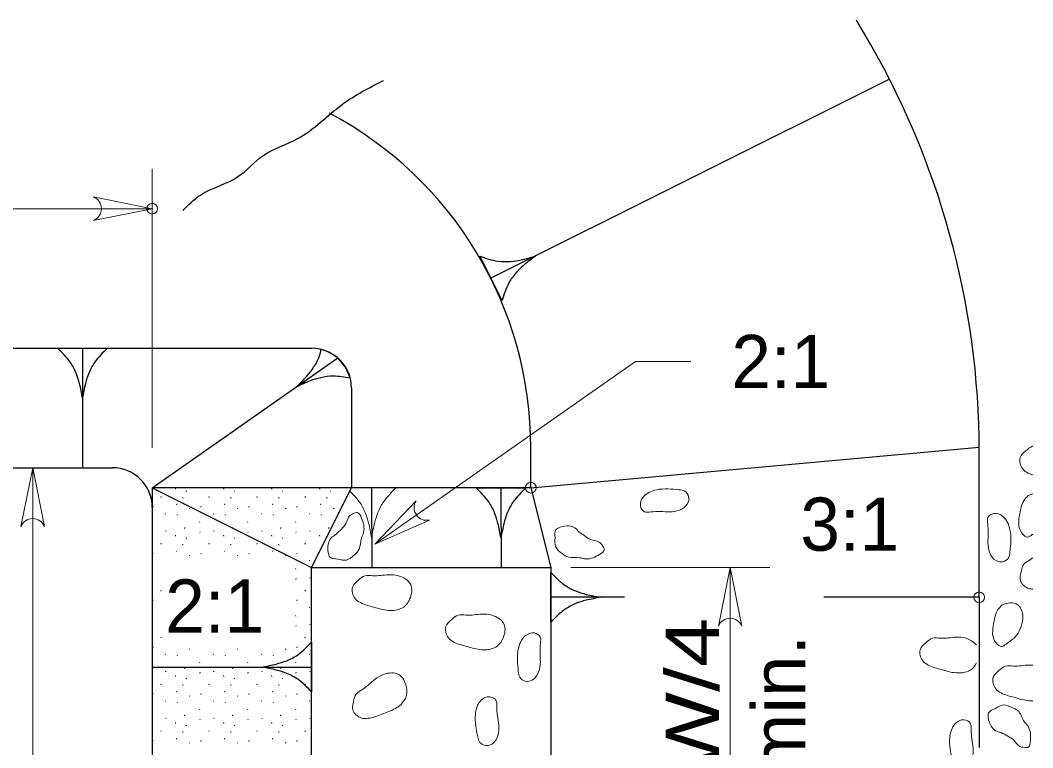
# Model space of a CAD drawing. Extents: x 1043.1 to 1101.1, y 672.4 to 716.4.
# Drawn here: x 1060.033 to 1063.081, y 704.187 to 706.376 of the extents above; entities that cross this region are included whole.
import ezdxf

# ---------------------------------------------------------------- set-up
doc = ezdxf.new("R2010")
doc.units = 0
doc.header["$LTSCALE"] = 0.064
doc.header["$PDMODE"] = 32
doc.header["$PDSIZE"] = 0.032
doc.layers.add('1', color=7, linetype='Continuous', lineweight=13)

msp = doc.modelspace()

# ---------------------------------------------------------------- linework, layer by layer
at = {"layer": '1', "lineweight": 25}
for p, q in [((1062.64925, 706.19908), (1061.44983, 705.5995)), ((1061.48333, 705.53242), (1061.41633, 705.6665)), ((1060.14583, 705.38908), (1060.29575, 705.38908)), ((1060.22075, 705.38908), (1060.22075, 705.02725)), ((1060.43058, 704.96942), (1060.98883, 705.36)), ((1061.03033, 705.26925), (1061.03033, 704.96942)), ((1062.91942, 704.63958), (1062.91942, 705.11933)), ((1061.57008, 704.96942), (1062.91892, 705.09175)), ((1061.57008, 704.96942), (1061.57008, 705.08933)), ((1058.45158, 705.02933), (1060.31075, 705.02933)), ((1060.43058, 704.96942), (1060.91042, 704.7295)), ((1061.09033, 704.96942), (1061.09125, 704.7285)), ((1061.40525, 704.9685), (1061.55508, 704.9685)), ((1061.48008, 704.9685), (1061.48025, 704.72875)), ((1060.91042, 704.7295), (1061.63, 704.7295)), ((1061.63, 704.56458), (1061.63, 704.7145)), ((1061.85183, 704.63958), (1061.63, 704.63958)), ((1062.91942, 704.63958), (1062.45225, 704.63958)), ((1062.91942, 704.63958), (1062.91942, 704.18808)), ((1060.91042, 704.50458), (1060.91042, 704.35475)), ((1060.43058, 704.42975), (1060.91042, 704.42975))]:
    msp.add_line(p, q, dxfattribs=at)
at = {"layer": '1'}
for p, q in [((1060.43058, 705.92883), (1060.43058, 705.08933)), ((1058.33175, 705.80883), (1060.43058, 705.80883)), ((1060.50083, 704.96775), (1060.50108, 704.96492)), ((1060.64542, 704.96775), (1060.64575, 704.96492)), ((1060.79, 704.96775), (1060.79033, 704.96492)), ((1060.9345, 704.96775), (1060.93483, 704.96492)), ((1060.4565, 704.94025), (1060.45775, 704.94292)), ((1060.52142, 704.94025), (1060.52258, 704.93842)), ((1060.52258, 704.9395), (1060.52392, 704.93775)), ((1060.53225, 704.95975), (1060.53342, 704.95783)), ((1060.601, 704.94025), (1060.60233, 704.94292)), ((1060.666, 704.94025), (1060.66725, 704.93842)), ((1060.66725, 704.9395), (1060.66842, 704.93775)), ((1060.67675, 704.95975), (1060.67792, 704.95783)), ((1060.74575, 704.94025), (1060.74692, 704.94292)), ((1060.8105, 704.94025), (1060.81175, 704.93842)), ((1060.81175, 704.9395), (1060.81292, 704.93775)), ((1060.82125, 704.95975), (1060.82242, 704.95783)), ((1060.89025, 704.94025), (1060.89142, 704.94292)), ((1060.95508, 704.94025), (1060.95633, 704.93842)), ((1060.95633, 704.9395), (1060.9575, 704.93775)), ((1060.96592, 704.95975), (1060.96708, 704.95783)), ((1063.0805, 704.95133), (1063.06708, 704.94608)), ((1060.43208, 704.91092), (1060.43333, 704.91358)), ((1060.50358, 704.91783), (1060.50483, 704.92058)), ((1060.54292, 704.90742), (1060.54408, 704.90558)), ((1060.57675, 704.91092), (1060.57792, 704.91358)), ((1060.64808, 704.91783), (1060.64942, 704.92058)), ((1060.68742, 704.90742), (1060.68858, 704.90558)), ((1060.72125, 704.91092), (1060.72242, 704.91358)), ((1060.79283, 704.91783), (1060.794, 704.92058)), ((1060.832, 704.90742), (1060.83325, 704.90558)), ((1060.86575, 704.91092), (1060.867, 704.91358)), ((1060.93733, 704.91783), (1060.9385, 704.92058)), ((1060.97658, 704.90742), (1060.97783, 704.90558)), ((1060.46983, 704.89158), (1060.471, 704.88983)), ((1060.5055, 704.88833), (1060.50675, 704.8865)), ((1060.61433, 704.89158), (1060.6155, 704.88983)), ((1060.65, 704.88833), (1060.65125, 704.8865)), ((1060.759, 704.89158), (1060.76025, 704.88983)), ((1060.79458, 704.88833), (1060.79592, 704.8865)), ((1060.9035, 704.89158), (1060.90475, 704.88983)), ((1060.93925, 704.88833), (1060.94042, 704.8865)), ((1060.52783, 704.84658), (1060.529, 704.84933)), ((1060.57275, 704.86692), (1060.57392, 704.86508)), ((1060.67233, 704.84658), (1060.6735, 704.84933)), ((1060.71725, 704.86692), (1060.71842, 704.86508)), ((1060.81683, 704.84658), (1060.818, 704.84933)), ((1060.86175, 704.86692), (1060.86292, 704.86508)), ((1060.9615, 704.84658), (1060.96275, 704.84933)), ((1060.47092, 704.84008), (1060.47208, 704.83825)), ((1060.50083, 704.82658), (1060.50108, 704.82392)), ((1060.53225, 704.81858), (1060.53342, 704.81692)), ((1060.57375, 704.83425), (1060.57492, 704.83692)), ((1060.6155, 704.84008), (1060.61675, 704.83825)), ((1060.64542, 704.82658), (1060.64575, 704.82392)), ((1060.67675, 704.81858), (1060.67792, 704.81692)), ((1060.71825, 704.83425), (1060.71942, 704.83692)), ((1060.76008, 704.84008), (1060.76133, 704.83825)), ((1060.79, 704.82658), (1060.79033, 704.82392)), ((1060.82125, 704.81858), (1060.82242, 704.81692)), ((1060.86275, 704.83425), (1060.86392, 704.83692)), ((1060.90458, 704.84008), (1060.90583, 704.83825)), ((1060.9345, 704.82658), (1060.93483, 704.82392)), ((1060.4565, 704.79933), (1060.45775, 704.802)), ((1060.52142, 704.79933), (1060.52258, 704.7975)), ((1060.52258, 704.79858), (1060.52392, 704.79683)), ((1060.601, 704.79933), (1060.60233, 704.802)), ((1060.666, 704.79933), (1060.66725, 704.7975)), ((1060.66725, 704.79858), (1060.66842, 704.79683)), ((1060.74575, 704.79933), (1060.74692, 704.802)), ((1060.8105, 704.79933), (1060.81175, 704.7975)), ((1060.81175, 704.79858), (1060.81292, 704.79683)), ((1060.89025, 704.79933), (1060.89142, 704.802)), ((1060.43208, 704.77), (1060.43333, 704.77275)), ((1060.50358, 704.77692), (1060.50483, 704.77958)), ((1060.54292, 704.76642), (1060.54408, 704.76458)), ((1060.57675, 704.77), (1060.57792, 704.77275)), ((1060.64808, 704.77692), (1060.64942, 704.77958)), ((1060.68742, 704.76642), (1060.68858, 704.76458)), ((1060.72125, 704.77), (1060.72242, 704.77275)), ((1060.79283, 704.77692), (1060.794, 704.77958)), ((1060.832, 704.76642), (1060.83325, 704.76458)), ((1060.86575, 704.77), (1060.867, 704.77275)), ((1060.86175, 704.72592), (1060.86292, 704.72408)), ((1060.9035, 704.75058), (1060.90475, 704.74883)), ((1061.69, 704.7295), (1062.28975, 704.7295)), ((1062.16983, 704.7295), (1062.16983, 704.00992)), ((1060.86275, 704.69333), (1060.86392, 704.696)), ((1060.90458, 704.69908), (1060.90583, 704.69733)), ((1060.4565, 704.65825), (1060.45775, 704.661)), ((1060.89025, 704.65825), (1060.89142, 704.661)), ((1060.43208, 704.629), (1060.43333, 704.63175)), ((1060.86575, 704.629), (1060.867, 704.63175)), ((1060.9035, 704.60975), (1060.90475, 704.60792)), ((1060.86175, 704.585), (1060.86292, 704.58325)), ((1060.86275, 704.55233), (1060.86392, 704.55508)), ((1060.90458, 704.55825), (1060.90583, 704.55642)), ((1060.4565, 704.51733), (1060.45775, 704.52)), ((1060.89025, 704.51733), (1060.89142, 704.52)), ((1060.43208, 704.488), (1060.43333, 704.49075)), ((1060.54292, 704.48458), (1060.54408, 704.48275)), ((1060.68742, 704.48458), (1060.68858, 704.48275)), ((1060.832, 704.48458), (1060.83325, 704.48275)), ((1060.86575, 704.488), (1060.867, 704.49075)), ((1060.46983, 704.46883), (1060.471, 704.467)), ((1060.5055, 704.4655), (1060.50675, 704.46375)), ((1060.61433, 704.46883), (1060.6155, 704.467)), ((1060.65, 704.4655), (1060.65125, 704.46375)), ((1060.759, 704.46883), (1060.76025, 704.467)), ((1060.79458, 704.4655), (1060.79592, 704.46375)), ((1060.9035, 704.46883), (1060.90475, 704.467)), ((1060.47092, 704.41725), (1060.47208, 704.41542)), ((1060.52783, 704.42383), (1060.529, 704.4265)), ((1060.57275, 704.44408), (1060.57392, 704.44225)), ((1060.6155, 704.41725), (1060.61675, 704.41542)), ((1060.67233, 704.42383), (1060.6735, 704.4265)), ((1060.71725, 704.44408), (1060.71842, 704.44225)), ((1060.76008, 704.41725), (1060.76133, 704.41542)), ((1060.81683, 704.42383), (1060.818, 704.4265)), ((1060.86175, 704.44408), (1060.86292, 704.44225)), ((1060.90458, 704.41725), (1060.90583, 704.41542)), ((1060.50083, 704.40383), (1060.50108, 704.40108)), ((1060.53225, 704.39583), (1060.53342, 704.394)), ((1060.57375, 704.41142), (1060.57492, 704.41408)), ((1060.64542, 704.40383), (1060.64575, 704.40108)), ((1060.67675, 704.39583), (1060.67792, 704.394)), ((1060.71825, 704.41142), (1060.71942, 704.41408)), ((1060.79, 704.40383), (1060.79033, 704.40108)), ((1060.82125, 704.39583), (1060.82242, 704.394)), ((1060.86275, 704.41142), (1060.86392, 704.41408)), ((1060.4565, 704.37642), (1060.45775, 704.37908)), ((1060.50358, 704.354), (1060.50483, 704.35675)), ((1060.52142, 704.37642), (1060.52258, 704.37458)), ((1060.52258, 704.37575), (1060.52392, 704.37392)), ((1060.601, 704.37642), (1060.60233, 704.37908)), ((1060.64808, 704.354), (1060.64942, 704.35675)), ((1060.666, 704.37642), (1060.66725, 704.37458)), ((1060.66725, 704.37575), (1060.66842, 704.37392)), ((1060.74575, 704.37642), (1060.74692, 704.37908)), ((1060.79283, 704.354), (1060.794, 704.35675)), ((1060.8105, 704.37642), (1060.81175, 704.37458)), ((1060.81175, 704.37575), (1060.81292, 704.37392)), ((1060.89025, 704.37642), (1060.89142, 704.37908)), ((1060.43208, 704.347), (1060.43333, 704.34983)), ((1060.46983, 704.32775), (1060.471, 704.32592)), ((1060.54292, 704.3435), (1060.54408, 704.34175)), ((1060.57675, 704.347), (1060.57792, 704.34983)), ((1060.61433, 704.32775), (1060.6155, 704.32592)), ((1060.68742, 704.3435), (1060.68858, 704.34175)), ((1060.72125, 704.347), (1060.72242, 704.34983)), ((1060.759, 704.32775), (1060.76025, 704.32592)), ((1060.832, 704.3435), (1060.83325, 704.34175)), ((1060.86575, 704.347), (1060.867, 704.34983)), ((1060.9035, 704.32775), (1060.90475, 704.32592)), ((1060.5055, 704.3245), (1060.50675, 704.32258)), ((1060.57275, 704.30308), (1060.57392, 704.30133)), ((1060.65, 704.3245), (1060.65125, 704.32258)), ((1060.71725, 704.30308), (1060.71842, 704.30133)), ((1060.79458, 704.3245), (1060.79592, 704.32258)), ((1060.86175, 704.30308), (1060.86292, 704.30133)), ((1060.47092, 704.27633), (1060.47208, 704.2745)), ((1060.52783, 704.28283), (1060.529, 704.28558)), ((1060.57375, 704.2705), (1060.57492, 704.27325)), ((1060.6155, 704.27633), (1060.61675, 704.2745)), ((1060.67233, 704.28283), (1060.6735, 704.28558)), ((1060.71825, 704.2705), (1060.71942, 704.27325)), ((1060.76008, 704.27633), (1060.76133, 704.2745)), ((1060.81683, 704.28283), (1060.818, 704.28558)), ((1060.86275, 704.2705), (1060.86392, 704.27325)), ((1060.90458, 704.27633), (1060.90583, 704.2745)), ((1060.4565, 704.23542), (1060.45775, 704.23825)), ((1060.50083, 704.26292), (1060.50108, 704.26025)), ((1060.52142, 704.23542), (1060.52258, 704.23358)), ((1060.52258, 704.23475), (1060.52392, 704.23292)), ((1060.53225, 704.25492), (1060.53342, 704.25308)), ((1060.601, 704.23542), (1060.60233, 704.23825)), ((1060.64542, 704.26292), (1060.64575, 704.26025)), ((1060.666, 704.23542), (1060.66725, 704.23358)), ((1060.66725, 704.23475), (1060.66842, 704.23292)), ((1060.67675, 704.25492), (1060.67792, 704.25308)), ((1060.74575, 704.23542), (1060.74692, 704.23825)), ((1060.79, 704.26292), (1060.79033, 704.26025)), ((1060.8105, 704.23542), (1060.81175, 704.23358)), ((1060.81175, 704.23475), (1060.81292, 704.23292)), ((1060.82125, 704.25492), (1060.82242, 704.25308)), ((1060.89025, 704.23542), (1060.89142, 704.23825)), ((1060.43208, 704.20608), (1060.43333, 704.20883)), ((1060.50358, 704.21308), (1060.50483, 704.21583)), ((1060.57675, 704.20608), (1060.57792, 704.20883)), ((1060.64808, 704.21308), (1060.64942, 704.21583)), ((1060.72125, 704.20608), (1060.72242, 704.20883)), ((1060.79283, 704.21308), (1060.794, 704.21583)), ((1060.86575, 704.20608), (1060.867, 704.20883)), ((1060.54292, 704.20258), (1060.54408, 704.20083)), ((1060.68742, 704.20258), (1060.68858, 704.20083)), ((1060.832, 704.20258), (1060.83325, 704.20083))]:
    msp.add_line(p, q, dxfattribs=at)
for points in [[(1060.254, 705.84417), (1060.43058, 705.80883), (1060.254, 705.77358), (1060.254, 705.77367)], [(1061.10033, 704.79983), (1061.88458, 705.34892), (1062.05125, 705.34892)], [(1060.0355, 704.85275), (1060.07083, 705.02933), (1060.10617, 704.85275), (1060.10608, 704.85275)], [(1060.07083, 705.02933), (1060.07083, 704.30983), (1060.07083, 703.83)], [(1061.16533, 704.96975), (1061.0305, 704.96933), (1061.025, 704.95908)], [(1061.26517, 704.87217), (1061.10033, 704.79983), (1061.22467, 704.93), (1061.22467, 704.92992)], [(1062.1345, 704.55292), (1062.16983, 704.7295), (1062.20517, 704.55292), (1062.20508, 704.55292)]]:
    msp.add_lwpolyline(points, dxfattribs=at)
at = {"layer": '1', "lineweight": 25}
for points in [[(1057.91192, 705.38908), (1059.41108, 705.38908), (1060.91042, 705.38908)], [(1061.02583, 705.2995), (1061.01208, 705.3325), (1060.98942, 705.35975), (1060.96225, 705.37708), (1060.9375, 705.3865)], [(1060.43058, 704.96942), (1060.43058, 704.90942), (1060.43058, 703.95), (1060.43058, 703.89), (1061.03033, 703.77008)], [(1061.57008, 704.96942), (1061.39808, 704.96942), (1060.43058, 704.96942)], [(1061.03033, 703.77008), (1060.91042, 704.00992), (1060.91042, 704.7295), (1061.03033, 704.96942)], [(1061.57008, 704.96942), (1061.63, 704.7295), (1061.63, 704.00992), (1061.57008, 703.77008)]]:
    msp.add_lwpolyline(points, dxfattribs=at)
at = {"layer": '1'}
for centre, start, end in [((1060.23967, 705.80894), 292.08789, 67.91402), ((1061.25669, 704.90927), 147.08522, 282.91135), ((1060.0708, 704.83842), 22.08789, 157.91402), ((1062.1698, 704.53859), 22.08789, 157.91402)]:
    msp.add_arc(centre, 0.03811, start, end, dxfattribs=at)
at = {"layer": '1', "lineweight": 25}
for centre, major_axis, start_param, end_param in [((1060.43863, 705.07247), (2.48123, 0), 0.0188725, 0.5531943), ((1060.43065, 705.0893), (1.13943, 0), 6.2831853, 7.3670824), ((1060.91041, 705.26919), (0.11994, 0), 6.2831853, 7.8539816), ((1060.31071, 704.90941), (0.11994, 0), 6.2831853, 7.8539816)]:
    msp.add_ellipse(centre, major_axis=major_axis, ratio=0.999895, start_param=start_param, end_param=end_param, dxfattribs=at)
for points in [[(1060.5225, 705.80342), (1060.57425, 705.84908), (1060.68858, 705.90542), (1060.76333, 705.96792), (1060.8685, 706.02), (1061.0025, 706.12283), (1061.12642, 706.19475)], [(1061.41633, 705.6665), (1061.471, 705.65108), (1061.50842, 705.65008), (1061.54092, 705.655), (1061.584, 705.6665)], [(1061.584, 705.6665), (1061.549, 705.639), (1061.5255, 705.616), (1061.50392, 705.58542), (1061.48333, 705.53242)], [(1060.22075, 705.23925), (1060.21175, 705.28283), (1060.20158, 705.31408), (1060.184, 705.347), (1060.14583, 705.38908)], [(1060.29575, 705.38908), (1060.2575, 705.347), (1060.23983, 705.31408), (1060.22975, 705.28283), (1060.22075, 705.23925)], [(1060.9375, 705.3865), (1060.93325, 705.366), (1060.91633, 705.33258), (1060.8965, 705.3065), (1060.86592, 705.27408)], [(1060.86592, 705.27408), (1060.90683, 705.29175), (1060.93825, 705.30142), (1060.97542, 705.30583), (1061.02583, 705.2995)], [(1061.48025, 704.8185), (1061.47108, 704.86208), (1061.461, 704.89342), (1061.44333, 704.92642), (1061.40525, 704.9685)], [(1061.55508, 704.9685), (1061.51692, 704.92642), (1061.49925, 704.89342), (1061.48908, 704.86208), (1061.48025, 704.8185)], [(1061.63, 704.7145), (1061.67208, 704.67633), (1061.70508, 704.65858), (1061.73642, 704.6485), (1061.78, 704.63958)], [(1061.78, 704.63958), (1061.73642, 704.63058), (1061.70508, 704.6205), (1061.67208, 704.60283), (1061.63, 704.56458)], [(1060.7605, 704.42975), (1060.80408, 704.43875), (1060.83533, 704.44883), (1060.86833, 704.4665), (1060.91042, 704.50458)], [(1060.91042, 704.35475), (1060.86833, 704.39292), (1060.83533, 704.41058), (1060.80408, 704.42075), (1060.7605, 704.42975)]]:
    msp.add_spline(points, degree=3, dxfattribs=at)
at = {"layer": '1'}
for points in [[(1063.0805, 705.09425), (1063.07992, 705.09408), (1063.05958, 705.08042), (1063.04283, 705.06025), (1063.05025, 705.02583), (1063.06633, 705.01325), (1063.0805, 705.00792)], [(1061.09092, 704.8195), (1061.09975, 704.863), (1061.10975, 704.89442), (1061.12733, 704.92742), (1061.16533, 704.96975)], [(1061.98775, 704.89633), (1062.01683, 704.90175), (1062.04158, 704.92108), (1062.045, 704.94192), (1062.03333, 704.95892), (1062.01608, 704.96308), (1061.94875, 704.96308), (1061.90858, 704.94192), (1061.89992, 704.9145), (1061.91208, 704.89692), (1061.93108, 704.89633), (1061.98775, 704.89633)], [(1061.025, 704.95908), (1061.05375, 704.92725), (1061.0715, 704.89425), (1061.08175, 704.863), (1061.09092, 704.8195)], [(1063.06708, 704.94608), (1063.05333, 704.93025), (1063.04442, 704.90533), (1063.039, 704.87483), (1063.04058, 704.84683), (1063.04992, 704.83058), (1063.06442, 704.82083), (1063.07883, 704.82842), (1063.0805, 704.8295)], [(1061.067, 704.85783), (1061.06058, 704.878), (1061.04733, 704.89483), (1061.03725, 704.89183), (1061.02475, 704.88458), (1061.01342, 704.86175), (1060.99975, 704.84492), (1060.98292, 704.82833), (1060.9695, 704.81825), (1060.96075, 704.80133), (1060.95992, 704.77475), (1060.96542, 704.76083), (1060.98875, 704.75408), (1061.01525, 704.75158), (1061.03908, 704.76775), (1061.05308, 704.784), (1061.06008, 704.8175), (1061.06675, 704.83425), (1061.067, 704.85783)], [(1062.94508, 704.80408), (1062.9505, 704.775), (1062.96992, 704.75008), (1062.99075, 704.74675), (1063.00775, 704.7585), (1063.01192, 704.77575), (1063.01192, 704.843), (1062.99075, 704.88308), (1062.96333, 704.89183), (1062.94575, 704.87958), (1062.94508, 704.86058), (1062.94508, 704.80408)], [(1061.75783, 704.75858), (1061.77683, 704.76842), (1061.79125, 704.78408), (1061.78642, 704.79375), (1061.77742, 704.80483), (1061.75283, 704.81208), (1061.73425, 704.82292), (1061.71492, 704.83675), (1061.70283, 704.84833), (1061.6845, 704.85433), (1061.65825, 704.85042), (1061.64542, 704.84283), (1061.64275, 704.81875), (1061.6445, 704.792), (1061.66458, 704.77108), (1061.68292, 704.76025), (1061.71708, 704.75875), (1061.7345, 704.755), (1061.75783, 704.75858)], [(1063.0805, 704.7585), (1063.073, 704.7525), (1063.05392, 704.73892), (1063.04533, 704.71592), (1063.04342, 704.68975), (1063.06942, 704.666), (1063.0805, 704.664)], [(1061.16192, 704.6005), (1061.184, 704.60808), (1061.20533, 704.63375), (1061.20842, 704.67775), (1061.17175, 704.70433), (1061.14158, 704.70742), (1061.09442, 704.70433), (1061.07092, 704.70433), (1061.05058, 704.69058), (1061.03383, 704.67042), (1061.04125, 704.63608), (1061.05733, 704.6235), (1061.09792, 704.60992), (1061.14158, 704.60008), (1061.16192, 704.6005)], [(1062.9885, 704.61658), (1062.97475, 704.60075), (1062.96583, 704.57583), (1062.96042, 704.54533), (1062.962, 704.51733), (1062.97133, 704.50108), (1062.98583, 704.49125), (1063.00025, 704.49892), (1063.02458, 704.51683), (1063.03958, 704.53742), (1063.04933, 704.567), (1063.04692, 704.601), (1063.03533, 704.61733), (1063.01242, 704.623), (1062.9885, 704.61658)], [(1061.4425, 704.48208), (1061.46458, 704.48975), (1061.48592, 704.51525), (1061.48908, 704.55933), (1061.45233, 704.58592), (1061.42225, 704.589), (1061.37508, 704.58592), (1061.35158, 704.58592), (1061.33133, 704.57225), (1061.3145, 704.552), (1061.32192, 704.51758), (1061.338, 704.505), (1061.37858, 704.49142), (1061.42225, 704.48175), (1061.4425, 704.48208)], [(1061.599, 704.44458), (1061.59358, 704.4155), (1061.57425, 704.39058), (1061.55342, 704.38725), (1061.53642, 704.399), (1061.53225, 704.41625), (1061.53225, 704.48358), (1061.55342, 704.52358), (1061.58083, 704.53233), (1061.59842, 704.52008), (1061.599, 704.50108), (1061.599, 704.44458)], [(1062.91133, 704.49692), (1062.88, 704.5165), (1062.84992, 704.51958), (1062.80275, 704.5165), (1062.77925, 704.5165), (1062.759, 704.50283), (1062.74225, 704.48258), (1062.74958, 704.44825), (1062.76575, 704.43558), (1062.80625, 704.422), (1062.84992, 704.41233), (1062.87025, 704.41275)], [(1062.87025, 704.41275), (1062.89233, 704.42025), (1062.91133, 704.442)], [(1063.0805, 704.43558), (1063.06933, 704.43575), (1063.02208, 704.43258), (1062.99858, 704.43258), (1062.97842, 704.41892), (1062.96158, 704.39875), (1062.96892, 704.36442), (1062.985, 704.35183), (1063.02558, 704.33825), (1063.06933, 704.32842), (1063.0805, 704.32842)], [(1061.17933, 704.31742), (1061.19292, 704.33633), (1061.19542, 704.3695), (1061.17242, 704.40733), (1061.127, 704.40758), (1061.10075, 704.39258), (1061.064, 704.36275), (1061.04492, 704.34908), (1061.03633, 704.32608), (1061.03442, 704.3), (1061.06042, 704.27633), (1061.08083, 704.27542), (1061.12183, 704.28792), (1061.163, 704.30533), (1061.17933, 704.31742)], [(1061.47375, 704.25542), (1061.47158, 704.22583), (1061.45508, 704.19892), (1061.43483, 704.19333), (1061.41658, 704.20308), (1061.4105, 704.21975), (1061.40308, 704.28675), (1061.41958, 704.32883), (1061.44592, 704.3405), (1061.46483, 704.33033), (1061.4675, 704.31158), (1061.47375, 704.25542)], [(1063.0735, 704.22942), (1063.07333, 704.20808), (1063.06575, 704.188), (1063.05525, 704.188), (1063.04125, 704.191), (1063.02358, 704.20983), (1063.0055, 704.22158), (1062.98442, 704.2325), (1062.96875, 704.23825), (1062.95525, 704.25175), (1062.94675, 704.27708), (1062.94783, 704.29192), (1062.96808, 704.30525), (1062.99275, 704.3155), (1063.0205, 704.307), (1063.0385, 704.29558), (1063.055, 704.26558), (1063.06633, 704.25175), (1063.0735, 704.22942)], [(1062.90142, 704.186), (1062.89933, 704.15642), (1062.88283, 704.1295), (1062.8625, 704.12392), (1062.84433, 704.13375), (1062.83825, 704.15033), (1062.83075, 704.21733), (1062.84733, 704.25942), (1062.87358, 704.27108), (1062.8925, 704.26092), (1062.89525, 704.24225), (1062.90142, 704.186)]]:
    msp.add_spline(points, degree=3, dxfattribs=at)
for p in [(1060.43058, 705.80883), (1061.57008, 704.96942), (1062.91942, 704.63958)]:
    msp.add_point(p, dxfattribs=at)

# ---------------------------------------------------------------- texts
for s, p in [('2:1', (1062.17358, 705.26908)), ('3:1', (1062.38125, 704.77975)), ('2:1', (1060.46975, 704.53333))]:
    msp.add_text(s, height=0.16, dxfattribs=at).set_placement(p)
for s, width, p in [('W/4', 1.25, (1062.13583, 704.1025)), ('min.', 1.05, (1062.39583, 704.1025))]:
    msp.add_text(s, height=0.16, rotation=90, dxfattribs=dict(at, width=width)).set_placement(p)

doc.saveas('drawing.dxf')
